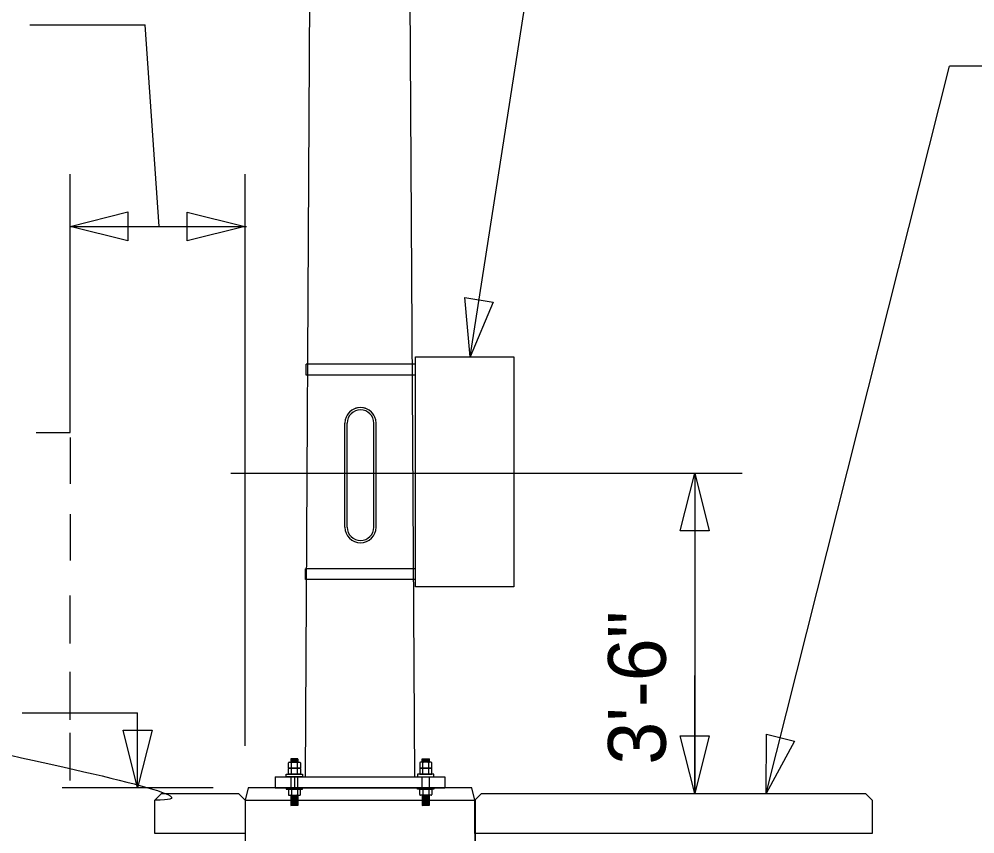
# Model space of a CAD drawing. Extents: x 1299104.8 to 1299141.6, y 239639.8 to 239661.8.
# Drawn here: x 1299125.724 to 1299127.71, y 239644.27 to 239645.963 of the extents above; entities that cross this region are included whole.
import ezdxf

# ---------------------------------------------------------------- set-up
doc = ezdxf.new("R2010")
doc.units = 0
for name, color, linetype in [('DIM TXT', 7, 'Continuous'), ('Level 3', 7, 'Continuous'), ('Level 4', 7, 'Continuous'), ('Level 7', 7, 'Continuous'), ('Level 8', 7, 'Continuous')]:
    doc.layers.add(name, color=color, linetype=linetype)

msp = doc.modelspace()

# ---------------------------------------------------------------- linework, layer by layer
at = {"layer": 'Level 3'}
for p, q in [((1299126.3184197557, 239644.38835224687), (1299126.3752654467, 239653.9384284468)), ((1299126.545802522, 239644.38835224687), (1299126.48895683, 239653.9384284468)), ((1299126.319959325, 239645.22291190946), (1299126.3200946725, 239645.2456501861)), ((1299126.5469529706, 239645.2456501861), (1299126.3200946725, 239645.2456501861)), ((1299126.5469529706, 239645.22291190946), (1299126.319959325, 239645.22291190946)), ((1299126.400728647, 239644.9071444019), (1299126.400728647, 239645.12350899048)), ((1299126.4054236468, 239644.9071444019), (1299126.4054236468, 239645.12350899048)), ((1299126.4606999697, 239644.90714440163), (1299126.4606999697, 239645.12350899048)), ((1299126.4653949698, 239644.90714440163), (1299126.4653949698, 239645.12350899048)), ((1299125.7591618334, 239645.10415552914), (1299125.8298655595, 239645.10415552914)), ((1299125.8298655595, 239645.09346775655), (1299125.8298655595, 239644.99727780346)), ((1299125.8298655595, 239644.93397330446), (1299125.8298655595, 239644.83778335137)), ((1299126.3186058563, 239644.7983267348), (1299126.3187412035, 239644.82106501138)), ((1299126.5469529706, 239644.82106501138), (1299126.3187412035, 239644.82106501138)), ((1299126.5469529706, 239644.7983267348), (1299126.3186058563, 239644.7983267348)), ((1299125.829043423, 239644.76543535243), (1299125.829043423, 239644.6659568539)), ((1299125.829043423, 239644.6067630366), (1299125.829043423, 239644.50728453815)), ((1299125.829043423, 239644.4802549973), (1299125.829043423, 239644.38077649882)), ((1299126.2558894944, 239644.38835224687), (1299126.2558894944, 239644.36561397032)), ((1299126.2558894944, 239644.38835224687), (1299126.6083327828, 239644.38835224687)), ((1299126.432111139, 239644.38835224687), (1299126.545802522, 239644.38835224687)), ((1299126.6083327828, 239644.38835224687), (1299126.6083327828, 239644.36561397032)), ((1299126.0058592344, 239644.34003340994), (1299126.0196092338, 239644.35378340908)), ((1299126.0196092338, 239644.35378340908), (1299126.1796092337, 239644.35378340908)), ((1299126.1796092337, 239644.35378340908), (1299126.193359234, 239644.34003340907)), ((1299126.2558894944, 239644.36561397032), (1299126.6083327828, 239644.36561397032)), ((1299126.6708630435, 239644.34003340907), (1299126.6846130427, 239644.35378340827)), ((1299126.6846130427, 239644.35378340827), (1299127.4821130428, 239644.35378340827)), ((1299127.4821130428, 239644.35378340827), (1299127.4958630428, 239644.34003340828)), ((1299126.0058592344, 239644.27128340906), (1299126.0058592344, 239644.34003340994)), ((1299126.193359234, 239644.34003340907), (1299126.6708630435, 239644.34003340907)), ((1299126.193359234, 239644.34003340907), (1299126.193359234, 239643.35091836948)), ((1299126.193359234, 239644.34003340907), (1299126.1933592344, 239644.27128340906)), ((1299126.6708630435, 239644.34003340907), (1299126.6708630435, 239643.35091837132)), ((1299126.6708630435, 239644.27128340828), (1299126.6708630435, 239644.34003340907)), ((1299126.6709538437, 239644.34004351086), (1299126.6709538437, 239644.2057643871)), ((1299127.4958630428, 239644.34003340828), (1299127.4958630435, 239644.27128340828)), ((1299126.193359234, 239644.27128340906), (1299126.0058592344, 239644.27128340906)), ((1299127.4958630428, 239644.27128340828), (1299126.6708630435, 239644.27128340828))]:
    msp.add_line(p, q, dxfattribs=at)
for points in [[(1299126.5469529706, 239645.26093361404), (1299126.7515974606, 239645.26093361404), (1299126.7515974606, 239644.78342980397), (1299126.5469529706, 239644.78342980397)], [(1299126.6644679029, 239644.36561397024), (1299126.199754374, 239644.36561397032), (1299126.193359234, 239644.34003340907), (1299126.6708630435, 239644.34003340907)]]:
    msp.add_lwpolyline(points, close=True, dxfattribs=at)
for centre, radius, start, end in [((1299126.4330618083, 239645.12350899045), 0.032333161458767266, 5.2811021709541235e-08, 179.999999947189), ((1299126.433061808, 239645.12350899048), 0.03233316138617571, 22.622418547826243, 157.37758153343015), ((1299126.4330618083, 239645.12350899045), 0.027638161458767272, 5.2811021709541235e-08, 179.999999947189), ((1299126.4330618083, 239644.90714440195), 0.032333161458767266, 180.00000005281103, 359.999999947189), ((1299126.4330618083, 239644.90714440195), 0.027638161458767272, 180.00000005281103, 359.999999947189)]:
    msp.add_arc(centre, radius, start, end, dxfattribs=at)
msp.add_spline([(1299125.636235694, 239644.44863672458), (1299126.0058871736, 239644.34003340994), (1299126.0058592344, 239644.34003340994)], degree=3, dxfattribs=at)
at = {"layer": 'Level 4'}
for p, q in [((1299126.2832464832, 239644.40647181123), (1299126.2832464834, 239644.4174531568)), ((1299126.3081164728, 239644.40647181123), (1299126.2832464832, 239644.40647181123)), ((1299126.2847001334, 239644.41890680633), (1299126.306662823, 239644.41890680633)), ((1299126.2847001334, 239644.40647181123), (1299126.306662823, 239644.40647181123)), ((1299126.2894639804, 239644.4064718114), (1299126.2894639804, 239644.41890680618)), ((1299126.2894639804, 239644.39403681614), (1299126.2894639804, 239644.4064718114)), ((1299126.3018989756, 239644.4064718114), (1299126.3018989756, 239644.41890680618)), ((1299126.3018989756, 239644.39403681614), (1299126.3018989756, 239644.4064718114)), ((1299126.3081164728, 239644.41745315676), (1299126.3081164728, 239644.40647181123)), ((1299126.5561058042, 239644.4174531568), (1299126.5561058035, 239644.40647181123)), ((1299126.5561058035, 239644.40647181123), (1299126.5809757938, 239644.40647181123)), ((1299126.5795221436, 239644.41890680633), (1299126.5575594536, 239644.41890680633)), ((1299126.5795221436, 239644.40647181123), (1299126.5575594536, 239644.40647181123)), ((1299126.5623233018, 239644.4064718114), (1299126.5623233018, 239644.41890680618)), ((1299126.5623233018, 239644.39403681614), (1299126.5623233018, 239644.4064718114)), ((1299126.5747582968, 239644.4064718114), (1299126.5747582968, 239644.41890680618)), ((1299126.5747582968, 239644.39403681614), (1299126.5747582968, 239644.4064718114)), ((1299126.5809757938, 239644.40647181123), (1299126.580975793, 239644.4174531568)), ((1299126.2832464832, 239644.39403681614), (1299126.2832464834, 239644.40501816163)), ((1299126.3081164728, 239644.39403681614), (1299126.2832464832, 239644.39403681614)), ((1299126.2956814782, 239644.38835224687), (1299126.2956814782, 239644.36561397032)), ((1299126.3081164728, 239644.40501816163), (1299126.3081164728, 239644.39403681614)), ((1299126.5561058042, 239644.40501816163), (1299126.5561058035, 239644.39403681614)), ((1299126.5561058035, 239644.39403681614), (1299126.5809757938, 239644.39403681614)), ((1299126.5809757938, 239644.39403681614), (1299126.580975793, 239644.40501816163)), ((1299126.3081164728, 239644.36277168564), (1299126.2832464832, 239644.36277168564)), ((1299126.2832464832, 239644.36277168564), (1299126.2832464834, 239644.35179033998)), ((1299126.2847001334, 239644.35033669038), (1299126.306662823, 239644.35033669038)), ((1299126.2894639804, 239644.3627716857), (1299126.2894639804, 239644.3503366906)), ((1299126.3018989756, 239644.3627716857), (1299126.3018989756, 239644.3503366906)), ((1299126.3081164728, 239644.35179033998), (1299126.3081164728, 239644.36277168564)), ((1299126.5561058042, 239644.35179033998), (1299126.5561058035, 239644.36277168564)), ((1299126.5561058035, 239644.36277168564), (1299126.5809757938, 239644.36277168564)), ((1299126.5795221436, 239644.35033669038), (1299126.5575594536, 239644.35033669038)), ((1299126.5623233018, 239644.3627716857), (1299126.5623233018, 239644.3503366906)), ((1299126.5747582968, 239644.3627716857), (1299126.5747582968, 239644.3503366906)), ((1299126.5809757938, 239644.36277168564), (1299126.580975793, 239644.35179033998))]:
    msp.add_line(p, q, dxfattribs=at)
for points in [[(1299126.3027871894, 239644.41890680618), (1299126.3027871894, 239644.4260125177), (1299126.2885757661, 239644.4260125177), (1299126.2885757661, 239644.41890680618)], [(1299126.2885757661, 239644.4260125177), (1299126.3027871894, 239644.4260125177), (1299126.2885757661, 239644.42530194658), (1299126.2885757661, 239644.42459137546), (1299126.3027871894, 239644.42530194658), (1299126.3027871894, 239644.42459137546), (1299126.2885757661, 239644.4238808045), (1299126.2885757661, 239644.42317023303), (1299126.3027871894, 239644.4238808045), (1299126.3027871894, 239644.42317023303), (1299126.2885757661, 239644.42245966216), (1299126.2885757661, 239644.42174909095), (1299126.3027871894, 239644.42245966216), (1299126.3027871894, 239644.42174909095), (1299126.2885757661, 239644.42103851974), (1299126.2885757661, 239644.4203279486), (1299126.3027871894, 239644.42103851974), (1299126.3027871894, 239644.4203279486), (1299126.2885757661, 239644.41961737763), (1299126.2885757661, 239644.41890680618), (1299126.3027871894, 239644.41961737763), (1299126.3027871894, 239644.41890680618)], [(1299126.5614350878, 239644.41890680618), (1299126.5614350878, 239644.4260125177), (1299126.57564651, 239644.4260125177), (1299126.57564651, 239644.41890680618)], [(1299126.5614350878, 239644.4260125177), (1299126.57564651, 239644.4260125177), (1299126.5614350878, 239644.42530194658), (1299126.5614350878, 239644.42459137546), (1299126.57564651, 239644.42530194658), (1299126.57564651, 239644.42459137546), (1299126.5614350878, 239644.4238808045), (1299126.5614350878, 239644.42317023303), (1299126.57564651, 239644.4238808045), (1299126.57564651, 239644.42317023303), (1299126.5614350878, 239644.42245966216), (1299126.5614350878, 239644.42174909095), (1299126.57564651, 239644.42245966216), (1299126.57564651, 239644.42174909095), (1299126.5614350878, 239644.42103851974), (1299126.5614350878, 239644.4203279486), (1299126.57564651, 239644.42103851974), (1299126.57564651, 239644.4203279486), (1299126.5614350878, 239644.41961737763), (1299126.5614350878, 239644.41890680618), (1299126.57564651, 239644.41961737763), (1299126.57564651, 239644.41890680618)], [(1299126.3027871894, 239644.36561397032), (1299126.3027871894, 239644.38835224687), (1299126.2885757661, 239644.38835224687), (1299126.2885757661, 239644.36561397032)], [(1299126.5614350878, 239644.36561397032), (1299126.5614350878, 239644.38835224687), (1299126.57564651, 239644.38835224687), (1299126.57564651, 239644.36561397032)], [(1299126.2885757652, 239644.3503366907), (1299126.3027871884, 239644.3503366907), (1299126.2885757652, 239644.3496261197), (1299126.2885757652, 239644.34891554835), (1299126.3027871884, 239644.3496261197), (1299126.3027871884, 239644.34891554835), (1299126.2885757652, 239644.34820497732), (1299126.2885757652, 239644.3474944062), (1299126.3027871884, 239644.34820497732), (1299126.3027871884, 239644.3474944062), (1299126.2885757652, 239644.34678383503), (1299126.2885757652, 239644.34607326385), (1299126.3027871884, 239644.34678383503), (1299126.3027871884, 239644.34607326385), (1299126.2885757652, 239644.3453626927), (1299126.2885757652, 239644.34465212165), (1299126.3027871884, 239644.3453626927), (1299126.3027871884, 239644.34465212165), (1299126.2885757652, 239644.34394155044), (1299126.2885757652, 239644.3432309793), (1299126.3027871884, 239644.34394155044), (1299126.3027871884, 239644.3432309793), (1299126.2885757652, 239644.3425204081), (1299126.2885757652, 239644.34180983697), (1299126.3027871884, 239644.3425204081), (1299126.3027871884, 239644.34180983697), (1299126.2885757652, 239644.34109926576), (1299126.2885757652, 239644.34038869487), (1299126.3027871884, 239644.34109926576), (1299126.3027871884, 239644.34038869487), (1299126.2885757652, 239644.33967812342), (1299126.2885757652, 239644.33896755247), (1299126.3027871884, 239644.33967812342), (1299126.3027871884, 239644.33896755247), (1299126.2885757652, 239644.3382569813), (1299126.2885757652, 239644.33754641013), (1299126.3027871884, 239644.3382569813), (1299126.3027871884, 239644.33754641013), (1299126.2885757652, 239644.3368358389), (1299126.2885757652, 239644.33612526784), (1299126.3027871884, 239644.3368358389), (1299126.3027871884, 239644.33612526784), (1299126.2885757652, 239644.33541469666), (1299126.2885757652, 239644.33470412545), (1299126.3027871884, 239644.33541469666), (1299126.3027871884, 239644.33470412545), (1299126.2885757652, 239644.33399355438), (1299126.2885757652, 239644.33328298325), (1299126.3027871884, 239644.33399355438), (1299126.3027871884, 239644.33328298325), (1299126.2885757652, 239644.33257241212), (1299126.2885757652, 239644.331861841), (1299126.3027871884, 239644.33257241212), (1299126.3027871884, 239644.331861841), (1299126.2885757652, 239644.3311512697), (1299126.2885757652, 239644.33044069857), (1299126.3027871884, 239644.3311512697), (1299126.3027871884, 239644.33044069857), (1299126.2885757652, 239644.32973012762), (1299126.2885757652, 239644.32901955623), (1299126.3027871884, 239644.32973012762), (1299126.3027871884, 239644.32901955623)], [(1299126.5614350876, 239644.3503366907), (1299126.5756465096, 239644.3503366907), (1299126.5614350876, 239644.3496261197), (1299126.5614350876, 239644.34891554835), (1299126.5756465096, 239644.3496261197), (1299126.5756465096, 239644.34891554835), (1299126.5614350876, 239644.34820497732), (1299126.5614350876, 239644.3474944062), (1299126.5756465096, 239644.34820497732), (1299126.5756465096, 239644.3474944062), (1299126.5614350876, 239644.34678383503), (1299126.5614350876, 239644.34607326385), (1299126.5756465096, 239644.34678383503), (1299126.5756465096, 239644.34607326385), (1299126.5614350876, 239644.3453626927), (1299126.5614350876, 239644.34465212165), (1299126.5756465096, 239644.3453626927), (1299126.5756465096, 239644.34465212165), (1299126.5614350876, 239644.34394155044), (1299126.5614350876, 239644.3432309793), (1299126.5756465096, 239644.34394155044), (1299126.5756465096, 239644.3432309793), (1299126.5614350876, 239644.3425204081), (1299126.5614350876, 239644.34180983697), (1299126.5756465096, 239644.3425204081), (1299126.5756465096, 239644.34180983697), (1299126.5614350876, 239644.34109926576), (1299126.5614350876, 239644.34038869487), (1299126.5756465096, 239644.34109926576), (1299126.5756465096, 239644.34038869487), (1299126.5614350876, 239644.33967812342), (1299126.5614350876, 239644.33896755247), (1299126.5756465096, 239644.33967812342), (1299126.5756465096, 239644.33896755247), (1299126.5614350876, 239644.3382569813), (1299126.5614350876, 239644.33754641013), (1299126.5756465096, 239644.3382569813), (1299126.5756465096, 239644.33754641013), (1299126.5614350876, 239644.3368358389), (1299126.5614350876, 239644.33612526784), (1299126.5756465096, 239644.3368358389), (1299126.5756465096, 239644.33612526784), (1299126.5614350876, 239644.33541469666), (1299126.5614350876, 239644.33470412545), (1299126.5756465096, 239644.33541469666), (1299126.5756465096, 239644.33470412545), (1299126.5614350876, 239644.33399355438), (1299126.5614350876, 239644.33328298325), (1299126.5756465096, 239644.33399355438), (1299126.5756465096, 239644.33328298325), (1299126.5614350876, 239644.33257241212), (1299126.5614350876, 239644.331861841), (1299126.5756465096, 239644.33257241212), (1299126.5756465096, 239644.331861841), (1299126.5614350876, 239644.3311512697), (1299126.5614350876, 239644.33044069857), (1299126.5756465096, 239644.3311512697), (1299126.5756465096, 239644.33044069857), (1299126.5614350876, 239644.32973012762), (1299126.5614350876, 239644.32901955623), (1299126.5756465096, 239644.32973012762), (1299126.5756465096, 239644.32901955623)]]:
    msp.add_lwpolyline(points, dxfattribs=at)
for points in [[(1299126.312735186, 239644.38835224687), (1299126.27862777, 239644.38835224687), (1299126.27862777, 239644.39403681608), (1299126.312735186, 239644.39403681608)], [(1299126.5514870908, 239644.38835224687), (1299126.5855945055, 239644.38835224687), (1299126.5855945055, 239644.39403681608), (1299126.5514870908, 239644.39403681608)], [(1299126.312735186, 239644.36561397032), (1299126.27862777, 239644.36561397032), (1299126.27862777, 239644.3627716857), (1299126.312735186, 239644.3627716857)], [(1299126.5514870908, 239644.36561397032), (1299126.5855945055, 239644.36561397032), (1299126.5855945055, 239644.3627716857), (1299126.5514870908, 239644.3627716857)]]:
    msp.add_lwpolyline(points, close=True, dxfattribs=at)
for centre, radius, start, end in [((1299126.2847001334, 239644.41745315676), 0.0014536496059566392, 89.99999999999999, 179.99999745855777), ((1299126.2847001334, 239644.40501816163), 0.0014536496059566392, 89.99999999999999, 179.99999745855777), ((1299126.2880103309, 239644.4174531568), 0.0014536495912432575, 8.98083385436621e-10, 90), ((1299126.2880103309, 239644.40501816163), 0.0014536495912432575, 8.98083385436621e-10, 90), ((1299126.3033526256, 239644.417453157), 0.001453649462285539, 90, 179.99999999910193), ((1299126.3033526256, 239644.40501816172), 0.001453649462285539, 90, 179.99999999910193), ((1299126.306662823, 239644.41745315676), 0.0014536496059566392, 8.471474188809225e-07, 90.00000000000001), ((1299126.306662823, 239644.40501816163), 0.0014536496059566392, 8.471474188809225e-07, 90.00000000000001), ((1299126.5575594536, 239644.41745315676), 0.0014536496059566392, 90, 179.9999974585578), ((1299126.5575594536, 239644.40501816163), 0.0014536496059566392, 90, 179.9999974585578), ((1299126.5608696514, 239644.4174531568), 0.0014536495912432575, 8.98083385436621e-10, 90), ((1299126.5608696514, 239644.40501816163), 0.0014536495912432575, 8.98083385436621e-10, 90), ((1299126.5762119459, 239644.417453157), 0.001453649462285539, 90, 179.99999999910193), ((1299126.5762119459, 239644.40501816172), 0.001453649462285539, 90, 179.99999999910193), ((1299126.5795221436, 239644.41745315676), 0.0014536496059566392, 2.5414422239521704e-06, 90.00000000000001), ((1299126.5795221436, 239644.40501816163), 0.0014536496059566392, 2.5414422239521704e-06, 90.00000000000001), ((1299126.2847001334, 239644.35179034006), 0.0014536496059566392, 180.00000338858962, 270), ((1299126.2880103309, 239644.35179033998), 0.0014536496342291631, 270, 359.99999999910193), ((1299126.3033526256, 239644.3517903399), 0.0014536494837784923, 179.9999997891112, 269.99999978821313), ((1299126.306662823, 239644.35179034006), 0.0014536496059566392, 270, 359.9999991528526), ((1299126.5575594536, 239644.35179034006), 0.0014536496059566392, 180.00000338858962, 270), ((1299126.5608696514, 239644.35179033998), 0.0014536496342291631, 269.99999978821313, 359.99999978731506), ((1299126.5762119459, 239644.3517903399), 0.0014536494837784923, 179.9999997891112, 269.99999978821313), ((1299126.5795221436, 239644.35179034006), 0.0014536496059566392, 270, 359.9999966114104)]:
    msp.add_arc(centre, radius, start, end, dxfattribs=at)
for centre, major_axis, start_param, end_param in [((1299126.2934776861, 239644.41745315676), (-0.004013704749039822, 4.915370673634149e-19), 4.71238898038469, 6.283185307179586), ((1299126.2934776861, 239644.40501816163), (-0.004013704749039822, 4.915370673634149e-19), 4.71238898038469, 6.283185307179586), ((1299126.2978852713, 239644.41745315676), (0.004013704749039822, 0), 0, 1.5707963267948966), ((1299126.2978852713, 239644.40501816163), (0.004013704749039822, 0), 0, 1.5707963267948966), ((1299126.5663370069, 239644.41745315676), (-0.004013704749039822, 4.915370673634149e-19), 4.71238898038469, 6.283185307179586), ((1299126.5663370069, 239644.40501816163), (-0.004013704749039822, 4.915370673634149e-19), 4.71238898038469, 6.283185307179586), ((1299126.5707445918, 239644.41745315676), (0.004013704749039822, 0), 0, 1.5707963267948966), ((1299126.5707445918, 239644.40501816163), (0.004013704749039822, 0), 0, 1.5707963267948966), ((1299126.2934776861, 239644.35179033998), (-0.004013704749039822, 4.915370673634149e-19), 0, 1.5707963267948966), ((1299126.2978852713, 239644.35179033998), (0.004013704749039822, 0), 4.71238898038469, 6.283185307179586), ((1299126.5663370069, 239644.35179033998), (-0.004013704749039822, 4.915370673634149e-19), 0, 1.5707963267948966), ((1299126.5707445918, 239644.35179033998), (0.004013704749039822, 0), 4.71238898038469, 6.283185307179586)]:
    msp.add_ellipse(centre, major_axis=major_axis, ratio=0.3621715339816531, start_param=start_param, end_param=end_param, dxfattribs=at)
at = {"layer": 'Level 7'}
msp.add_line((1299126.1635936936, 239645.01956471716), (1299127.2261341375, 239645.01956471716), dxfattribs=at)
at = {"layer": 'Level 8'}
for p, q in [((1299126.6608081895, 239645.26084539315), (1299126.965202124, 239647.2172642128)), ((1299125.7456985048, 239645.95085113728), (1299125.9856985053, 239645.95085113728)), ((1299126.0145929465, 239645.53207265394), (1299125.9856985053, 239645.95085113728)), ((1299127.2760841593, 239644.35378340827), (1299127.6565242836, 239645.86476605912)), ((1299127.8965242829, 239645.86476605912), (1299127.6565242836, 239645.86476605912)), ((1299125.8298655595, 239645.10415552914), (1299125.8298655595, 239645.64080304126)), ((1299126.193359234, 239644.45273960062), (1299126.193359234, 239645.64080304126)), ((1299125.8298655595, 239645.53207265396), (1299126.1962558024, 239645.53207265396)), ((1299127.1275640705, 239645.01956471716), (1299127.1273385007, 239644.78051831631)), ((1299127.1275640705, 239645.01956471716), (1299127.1275640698, 239644.3537834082)), ((1299127.1275640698, 239644.3537834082), (1299127.1274222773, 239644.59894255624)), ((1299125.7298508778, 239644.52186397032), (1299125.969850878, 239644.52186397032)), ((1299125.969850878, 239644.36561397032), (1299125.969850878, 239644.52186397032)), ((1299126.1266535, 239644.36561397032), (1299125.813048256, 239644.36561397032))]:
    msp.add_line(p, q, dxfattribs=at)
for points in [[(1299125.9498655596, 239645.50207265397), (1299125.8298655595, 239645.53207265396), (1299125.9498655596, 239645.56207265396)], [(1299126.0726629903, 239645.56181533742), (1299126.1926629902, 239645.53181533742), (1299126.0726629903, 239645.50181533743)], [(1299126.708900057, 239645.3748066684), (1299126.6608081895, 239645.26084539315), (1299126.6496133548, 239645.3840309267)], [(1299127.0974508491, 239644.8995930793), (1299127.1275640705, 239645.01956471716), (1299127.1574508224, 239644.8995364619)], [(1299125.999850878, 239644.48561397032), (1299125.969850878, 239644.36561397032), (1299125.939850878, 239644.48561397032)], [(1299127.1574946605, 239644.47380073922), (1299127.1275640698, 239644.3537834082), (1299127.0974946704, 239644.47376603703)], [(1299127.3344757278, 239644.46282663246), (1299127.2760841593, 239644.35378340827), (1299127.276291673, 239644.47747640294)]]:
    msp.add_lwpolyline(points, close=True, dxfattribs=at)

# ---------------------------------------------------------------- texts
at = {"layer": 'DIM TXT'}
msp.add_text('3\'-6"', height=0.12000000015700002, rotation=90, dxfattribs=at).set_placement((1299127.0672740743, 239644.41388823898))

doc.saveas('drawing.dxf')
